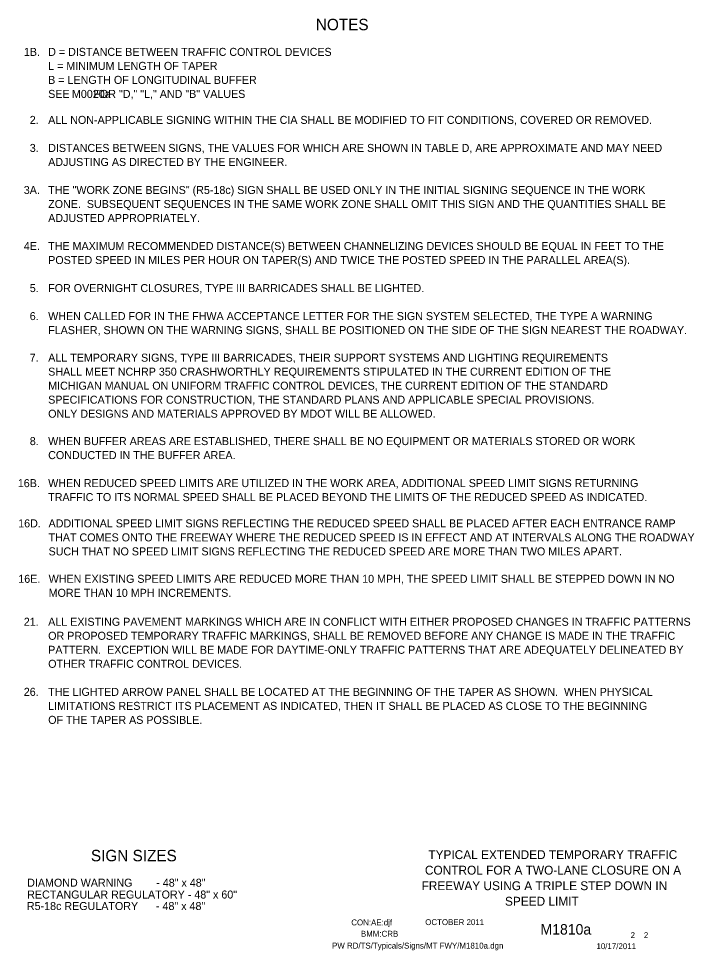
# Model space of a CAD drawing. Extents: x 16489 to 18480, y 5759 to 7026.
# Drawn here: x 17771 to 18480, y 5932 to 6909 of the extents above; entities that cross this region are included whole.
import ezdxf

# ---------------------------------------------------------------- set-up
doc = ezdxf.new("R2010")
doc.units = 0
for name, color, linetype in [('BORDER', 7, 'Continuous'), ('BORDER_SIGNAL_WO', 7, 'Continuous'), ('TYPICAL_TEXT_DIMEN_PR', 7, 'Continuous')]:
    doc.layers.add(name, color=color, linetype=linetype)

msp = doc.modelspace()

# ---------------------------------------------------------------- linework, layer by layer
at = {"layer": 'BORDER'}
msp.add_line((17909.25, 6035.02), (17909.25, 6035.02), dxfattribs=at)

# ---------------------------------------------------------------- texts
for s, p in [('TYPICAL EXTENDED TEMPORARY TRAFFIC', (18200.54, 6027.6)), ('CONTROL FOR A TWO-LANE CLOSURE ON A', (18196.92, 6011.3)), ('FREEWAY USING A TRIPLE STEP DOWN IN ', (18193.42, 5995)), ('SPEED LIMIT', (18280.92, 5978.7))]:
    msp.add_text(s, height=9.3, dxfattribs=at).set_placement(p)
at = {"layer": 'BORDER_SIGNAL_WO'}
for s, height, p in [('CON:AE:djf  ', 6.2, (18119.69, 5958.06)), ('    OCTOBER 2011', 6.2, (18188.08, 5958.34)), ('BMM:CRB', 6.2, (18129.81, 5946.17)), ('    M1810a   ', 11, (18301.86, 5948.38)), (' 2    2 ', 6.2, (18410.45, 5944.7)), ('PW RD/TS/Typicals/Signs/MT FWY/M1810a.dgn      ', 6.2, (18099.55, 5933.71)), ('10/17/2011', 6.2, (18376.93, 5933.13))]:
    msp.add_text(s, height=height, dxfattribs=at).set_placement(p)
at = {"layer": 'TYPICAL_TEXT_DIMEN_PR'}
for s, height, p in [('NOTES', 12, (18082.55, 6897)), ('1B.', 8.4, (17776.19, 6870.11)), ('D = DISTANCE BETWEEN TRAFFIC CONTROL DEVICES', 8.4, (17801.7, 6870.11)), ('L = MINIMUM LENGTH OF TAPER', 8.4, (17801.7, 6855.41)), ('B = LENGTH OF LONGITUDINAL BUFFER', 8.4, (17801.7, 6840.71)), ('SEE        FOR "D," "L," AND "B" VALUES', 8.4, (17801.7, 6826.01)), ('M0020a', 8.4, (17826.62, 6826.01)), ('2.', 8.4, (17782.39, 6798.75)), ('ALL NON-APPLICABLE SIGNING WITHIN THE CIA SHALL BE MODIFIED TO FIT CONDITIONS, COVERED OR REMOVED.', 8.4, (17801.7, 6798.75)), ('3.', 8.4, (17782.39, 6769.35)), ('DISTANCES BETWEEN SIGNS, THE VALUES FOR WHICH ARE SHOWN IN TABLE D, ARE APPROXIMATE AND MAY NEED', 8.4, (17801.7, 6769.35)), ('ADJUSTING AS DIRECTED BY THE ENGINEER.', 8.4, (17801.7, 6754.65)), ('THE "WORK ZONE BEGINS" (R5-18c) SIGN SHALL BE USED ONLY IN THE INITIAL SIGNING SEQUENCE IN THE WORK', 8.4, (17801.7, 6725.24)), ('3A.', 8.4, (17776.09, 6725.24)), ('ZONE.  SUBSEQUENT SEQUENCES IN THE SAME WORK ZONE SHALL OMIT THIS SIGN AND THE QUANTITIES SHALL BE', 8.4, (17801.7, 6710.54)), ('ADJUSTED APPROPRIATELY.', 8.4, (17801.7, 6695.84)), ('THE MAXIMUM RECOMMENDED DISTANCE(S) BETWEEN CHANNELIZING DEVICES SHOULD BE EQUAL IN FEET TO THE', 8.4, (17801.7, 6666.45)), ('4E.', 8.4, (17776.13, 6666.45)), ('POSTED SPEED IN MILES PER HOUR ON TAPER(S) AND TWICE THE POSTED SPEED IN THE PARALLEL AREA(S).', 8.4, (17801.7, 6651.75)), ('5.', 8.4, (17782.39, 6622.35)), ('FOR OVERNIGHT CLOSURES, TYPE III BARRICADES SHALL BE LIGHTED.', 8.4, (17801.7, 6622.35)), ('6.', 8.4, (17782.34, 6592.95)), ('WHEN CALLED FOR IN THE FHWA ACCEPTANCE LETTER FOR THE SIGN SYSTEM SELECTED, THE TYPE A WARNING ', 8.4, (17801.7, 6592.95)), ('FLASHER, SHOWN ON THE WARNING SIGNS, SHALL BE POSITIONED ON THE SIDE OF THE SIGN NEAREST THE ROADWAY.', 8.4, (17801.7, 6578.25)), ('7.', 8.4, (17782.34, 6549.34)), ('ALL TEMPORARY SIGNS, TYPE III BARRICADES, THEIR SUPPORT SYSTEMS AND LIGHTING REQUIREMENTS', 8.4, (17801.7, 6549.36)), ('SHALL MEET NCHRP 350 CRASHWORTHLY REQUIREMENTS STIPULATED IN THE CURRENT EDITION OF THE', 8.4, (17801.7, 6534.66)), ('MICHIGAN MANUAL ON UNIFORM TRAFFIC CONTROL DEVICES, THE CURRENT EDITION OF THE STANDARD', 8.4, (17801.7, 6519.96)), ('SPECIFICATIONS FOR CONSTRUCTION, THE STANDARD PLANS AND APPLICABLE SPECIAL PROVISIONS.', 8.4, (17801.7, 6505.26)), ('ONLY DESIGNS AND MATERIALS APPROVED BY MDOT WILL BE ALLOWED.', 8.4, (17801.7, 6490.56)), ('8.', 8.4, (17782.39, 6461.84)), ('WHEN BUFFER AREAS ARE ESTABLISHED, THERE SHALL BE NO EQUIPMENT OR MATERIALS STORED OR WORK     ', 8.4, (17801.7, 6461.84)), ('CONDUCTED IN THE BUFFER AREA.', 8.4, (17801.7, 6447.14)), ('16B.', 8.4, (17769.84, 6417.74)), ('WHEN REDUCED SPEED LIMITS ARE UTILIZED IN THE WORK AREA, ADDITIONAL SPEED LIMIT SIGNS RETURNING', 8.4, (17801.7, 6417.8)), ('TRAFFIC TO ITS NORMAL SPEED SHALL BE PLACED BEYOND THE LIMITS OF THE REDUCED SPEED AS INDICATED.', 8.4, (17801.7, 6403.1)), ('16D.', 8.4, (17770.23, 6375.53)), ('ADDITIONAL SPEED LIMIT SIGNS REFLECTING THE REDUCED SPEED SHALL BE PLACED AFTER EACH ENTRANCE RAMP', 8.4, (17802.09, 6375.53)), ('THAT COMES ONTO THE FREEWAY WHERE THE REDUCED SPEED IS IN EFFECT AND AT INTERVALS ALONG THE ROADWAY', 8.4, (17802.09, 6360.83)), ('SUCH THAT NO SPEED LIMIT SIGNS REFLECTING THE REDUCED SPEED ARE MORE THAN TWO MILES APART.', 8.4, (17802.09, 6346.13)), ('16E.', 8.4, (17770.33, 6317.37)), ('WHEN EXISTING SPEED LIMITS ARE REDUCED MORE THAN 10 MPH, THE SPEED LIMIT SHALL BE STEPPED DOWN IN NO', 8.4, (17802.19, 6317.37)), ('MORE THAN 10 MPH INCREMENTS.', 8.4, (17802.19, 6302.67)), ('21.', 8.4, (17776.14, 6272.32)), ('ALL EXISTING PAVEMENT MARKINGS WHICH ARE IN CONFLICT WITH EITHER PROPOSED CHANGES IN TRAFFIC PATTERNS', 8.4, (17801.7, 6272.32)), ('OR PROPOSED TEMPORARY TRAFFIC MARKINGS, SHALL BE REMOVED BEFORE ANY CHANGE IS MADE IN THE TRAFFIC', 8.4, (17801.7, 6257.62)), ('PATTERN.  EXCEPTION WILL BE MADE FOR DAYTIME-ONLY TRAFFIC PATTERNS THAT ARE ADEQUATELY DELINEATED BY', 8.4, (17801.7, 6242.92)), ('OTHER TRAFFIC CONTROL DEVICES.', 8.4, (17801.7, 6228.22)), ('26.', 8.4, (17776.09, 6198.82)), ('THE LIGHTED ARROW PANEL SHALL BE LOCATED AT THE BEGINNING OF THE TAPER AS SHOWN.  WHEN PHYSICAL', 8.4, (17801.7, 6198.82)), ('LIMITATIONS RESTRICT ITS PLACEMENT AS INDICATED, THEN IT SHALL BE PLACED AS CLOSE TO THE BEGINNING', 8.4, (17801.7, 6184.12)), ('OF THE TAPER AS POSSIBLE.', 8.4, (17801.7, 6169.42)), ('SIGN SIZES', 12, (17846.54, 6025.28)), ('DIAMOND WARNING        - 48" x 48"', 8.4, (17779.65, 5998.62)), ('RECTANGULAR REGULATORY - 48" x 60"', 8.4, (17779.65, 5986.22)), ('R5-18c REGULATORY      - 48" x 48"', 8.4, (17779.34, 5974.14))]:
    msp.add_text(s, height=height, dxfattribs=at).set_placement(p)

doc.saveas('drawing.dxf')
